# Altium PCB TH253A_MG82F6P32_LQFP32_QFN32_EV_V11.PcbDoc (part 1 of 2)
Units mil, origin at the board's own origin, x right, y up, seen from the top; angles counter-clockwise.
Board outline 3818.9 x 2637.8 mil, 2 copper layers (Top Layer, Bottom Layer); 102 components, 120 nets, 494 pads, 219 vias.
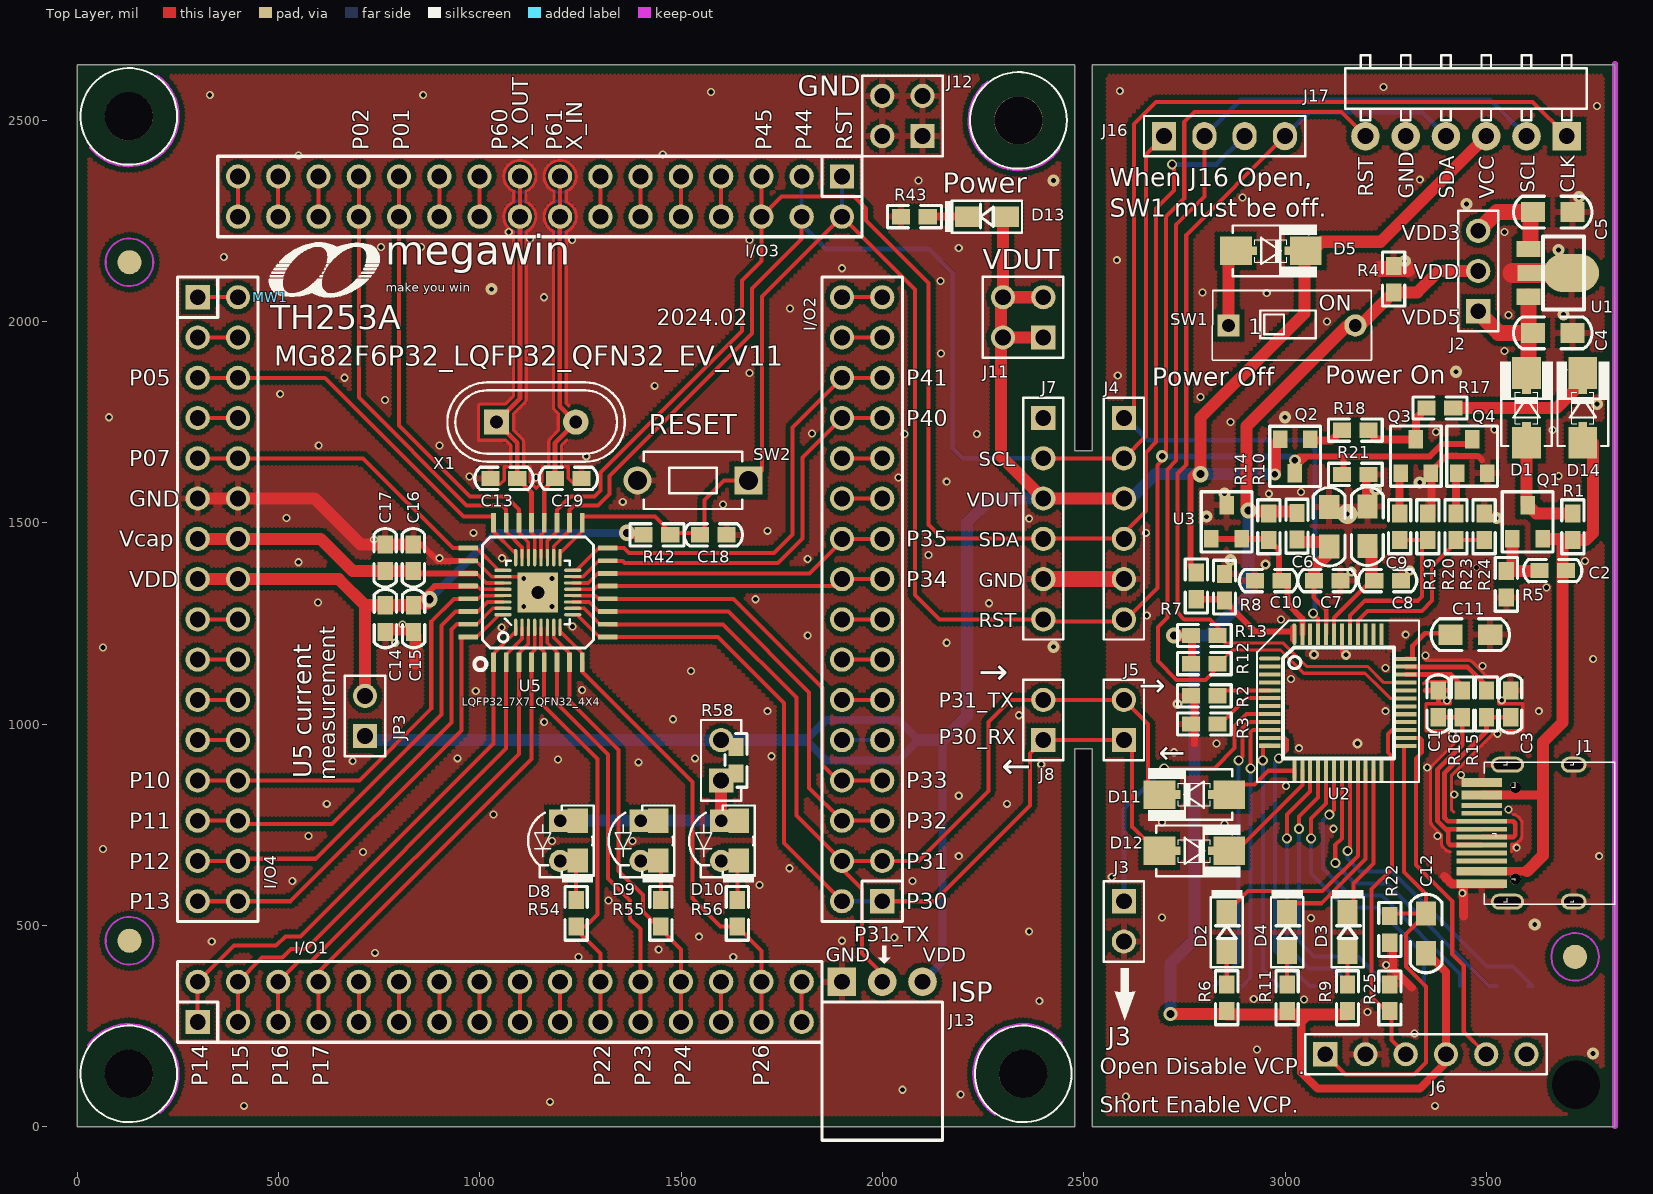
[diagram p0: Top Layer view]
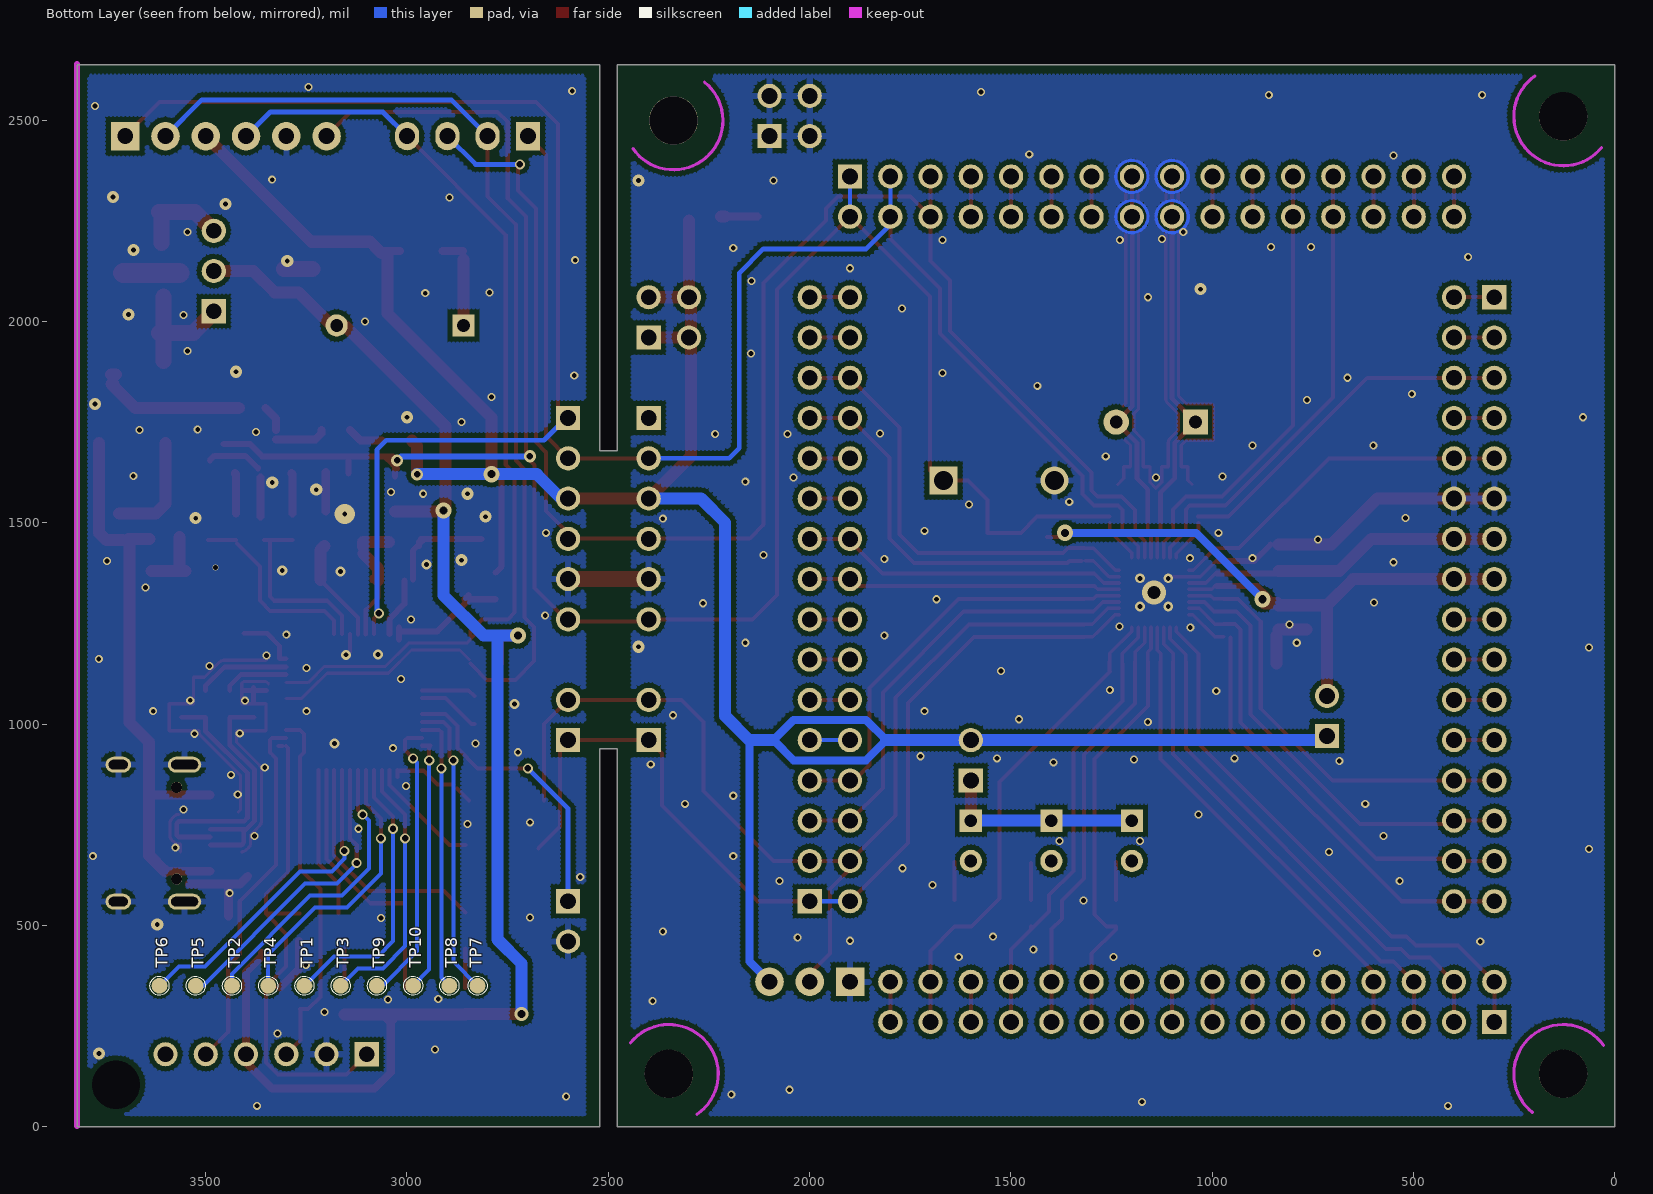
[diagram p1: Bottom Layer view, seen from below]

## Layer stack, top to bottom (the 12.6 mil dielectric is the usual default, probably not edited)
Top Layer: signal copper 1.4
Dielectric: dielectric 12.6, FR-4, Dk 4.8
Bottom Layer: signal copper 1.4

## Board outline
0,0 0,2637.8 2477.8,2637.8 2477.8,1678.74 2521.1,1678.74 2521.1,2637.8 3818.9,2637.8 3818.9,0 2521.1,0 2521.1,938.74 2477.8,938.74 2477.8,0

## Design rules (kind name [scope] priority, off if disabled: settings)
Clearance 12 [All] p1 off: gap=12
Clearance 7 [All] p2 off: gap=7
Clearance 6 [All] p3: gap=6
HoleSize 500-HoleSize [All] p1: absolutevalues=TRUE maxlimit=1500 minlimit=1 maxpercent=80.000 minpercent=20.000
PolygonConnect VIA [ISVIA] p1: connectstyle=Direct reliefconductorwidth=10 reliefentries=4 polygonreliefangle="90 Angle"
PolygonConnect "15 PolygonConnect" [All] p2: connectstyle=Relief reliefconductorwidth=15 reliefentries=4 polygonreliefangle="90 Angle"
RoomDefinition 1_MLink_V13 [InComponentClass('1_MLink_V13')] p1: confinementstyle=ConfineIn formatcopy=TRUE lockcomponents=FALSE outline -60,-105 3910,-105 3910,2750 -60,2750
RoomDefinition 2_TH253A_MG82F6P32_LQFP32_EV_V11 [InComponentClass('2_TH253A_MG82F6P32_LQFP32_EV_V11')] p2: confinementstyle=ConfineIn formatcopy=TRUE lockcomponents=FALSE outline -110,-40 3960,-40 3960,2710 -110,2710
RoutingVias [All] p1: holewidth=16 width=28 viastyle="Through Hole" minholewidth=16 minwidth=25 maxholewidth=28 maxwidth=50
ShortCircuit [All] p1 off: allowed=FALSE
SilkscreenOverComponentPads [All] p1: minsilkscreentomaskgap=10
SolderMaskExpansion [All] p1: expansion=4
UnRoutedNet [All] p1 off:
Width [All] p1: maxlimit=100 minlimit=6 preferedwidth=10
24 further rules are at their usual default settings.

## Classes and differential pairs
component class 2_TH253A_MG82F6P32_LQFP32_EV_V11: C13 C14 C15 C16 C17 C18 C19 D8 D9 D10 D13 I/O1 I/O2 I/O3 I/O4 J7 J8 J11 J12 J13 JP3 JP4 R42 R43 R54 R55 R56 R58 SW2 U5 X1
component class 1_MLink_V13: C1 C2 C3 C4 C5 C6 C7 C8 C9 C10 C11 C12 D1 D2 D3 D4 D5 D11 D12 D14 J1 J2 J3 J4 J5 J6 J16 J17 MW1 Q1 Q2 Q3 Q4 R1 R2 R3 R4 R5 R6 R7 R8 R9 R10 R11 R12 R13 R14 R15 R16 R17 R18 R19 R20 R21 R22 R23 R24 R25 SW1 TP1 TP2 TP3 TP4 TP5 TP6 TP7 TP8 TP9 TP10 U1 U2 U3

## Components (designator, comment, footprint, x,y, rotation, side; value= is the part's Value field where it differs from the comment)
C1 "15pF" 0603C#1 3380,1050 r270 top
C2 "0.1uF" 0603C#1 3664.41,1381.26 r0 top
C3 "15pF" 0603C#1 3560,1050 r270 top
C4 "4.7uF" 0805C 3664.41,1971.26 r0 top
C5 "4.7uF" 0805C 3664.41,2271.26 r0 top
C6 "4.7uF" 0805C 3109.41,1490 r90 top
C7 "0.1uF" 0603C#1 3104.45,1356.26 r0 top
C8 "0.1uF" 0603C#1 3254.45,1356.26 r0 top
C9 "4.7uF" 0805C 3204.41,1491.26 r90 top
C10 "0.1uF" 0603C#1 2958.5,1356.26 r0 top
C11 "4.7uF" 0805C 3460,1221.9 r0 top
C12 "4.7uF" 0805C 3350,480 r90 top
C13 "NC" 0603C#1 1060,1610 r0 top (schematic designator C18)
C14 "10uF" 0603C#2 765.55,1262 r270 top
C15 "0.1uF" 0603C#2 835.55,1262 r270 top
C16 "0.1uF" 0603C#2 835,1413 r90 top
C17 "4.7uF" 0603C#2 765,1413 r90 top
C18 "4.7uF" 0603C#2 1580,1470 r0 top (schematic designator C13)
C19 "NC" 0603C#1 1220,1610 r180 top
D1 "1N5817" DIODE_SMA_SOD323 3599.41,1785 r90 top
D2 "Yellow" 0805D 2855,483.26 r90 top
D3 "Green" 0805D 3155,483.26 r90 top
D4 "Red" 0805D 3005,483.26 r90 top
D5 "1N5817" DIODE_SMA_SOD323 2964.41,2175 r0 top
D8 "Red" LED38+0805 1199.45,710 r270 top
D9 "Yellow" LED38+0805 1399.45,710 r270 top
D10 "Green" LED38+0805 1599.45,710 r270 top
D11 "1N5817" DIODE_SMA_SOD323 2774.45,825 r180 top
D12 "1N5817" DIODE_SMA_SOD323 2774.45,685 r0 top
D13 "Yellow" 0805D 2259.45,2260 r180 top
D14 "1N5817" DIODE_SMA_SOD323 3739.41,1785 r90 top
I/O1 "CON16X2" PS16X2P254 299.45,260 r0 top locked
I/O2 "CON16X2" PS16X2P254 1999.45,560 r90 top locked
I/O3 "CON16X2" PS16X2P254 1899.45,2360 r180 top locked
I/O4 "CON16X2" PS16X2P254 299.45,2060 r270 top locked
J1 "CJ-USB3-C16P" USB_CF_16_SMD 3523.69,729.12 r90 top
J2 "2&3 (0 ohm)" PS3P254 3479.45,2025 r90 top
J3 "VCP Option" PS2P254 2599.45,560 r270 top locked
J4 "OnBoard ICP/SWD Connector" PS6P254 2599.45,1760 r270 top locked
J5 "NC" PS2P254 2599.45,960 r90 top locked
J6 "CON6" PS6P254 3099.45,180 r0 top
J7 "CON6" PS6P254 2399.45,1760 r270 top locked
J8 "NC" PS2P254 2399.45,960 r90 top
J11 "VDUT" PS2X2P254 2399.45,1960 r90 top
J12 "GND" PS2X2P254 2099.45,2460 r90 top
J13 "3P2.54_F_90" PS3P254f_90 1899.45,360 r0 top
J16 "When J16 Open, SW1 must be off." PS4P254 2699.45,2460 r0 top locked
J17 "Off Board ICP/SWD Connector" PS6P254_90 3699.45,2460 r180 top locked
JP3 "JUMPER_2" ps2p254 715,970 r90 top
MW1 "MW-A4" MEGAWIN_3.4 479.45,2060 r0 top
Q1 "IRLML6402" SOT23 3601.95,1501.97 r0 top
Q2 "2N3906" SOT23 3024.91,1665 r180 top
Q3 "3904" SOT23_132 3324.45,1665 r0 top
Q4 "3904" SOT23_132 3464.45,1665 r0 top
R1 "NC" 0603R 3714.45,1490 r270 top
R2 "0" 0603R 2799.45,1070 r0 top
R3 "NC" 0603R 2799.45,1000 r0 top
R4 "3.3K" 0603R 3269.45,2105 r270 top
R5 "1M" 0603R 3549.45,1347 r270 top
R6 "1K" 0603R 2855,320.26 r270 top
R7 "30K" 0603R 2779.45,1343 r90 top
R8 "10K" 0603R 2849.45,1340 r270 top
R9 "1K" 0603R 3155,320.26 r270 top
R10 "10" 0603R 3029.41,1491.26 r90 top
R11 "1K" 0603R 3005,320.26 r270 top
R12 "1.5K" 0603R 2799.45,1150 r180 top
R13 "1.5K" 0603R 2799.45,1220 r180 top
R14 "1K" 0603R 2959.41,1490 r270 top
R15 "30" 0603R 3500,1050 r90 top
R16 "30" 0603R 3440,1050 r90 top
R17 "4.7K" 0603R 3384.41,1785 r0 top
R18 "1K" 0603R 3174.45,1730 r0 top
R19 "4.7K" 0603R 3284.45,1490 r270 top
R20 "10K" 0603R 3354.45,1490 r270 top
R21 "1M" 0603R 3174.45,1620 r180 top
R22 "47K" 0603R 3260,490 r270 top
R23 "4.7K" 0603R 3424.45,1490 r270 top
R24 "10K" 0603R 3494.45,1490 r270 top
R25 "47K" 0603R 3260,320 r270 top
R42 "47K" 0603R 1440,1470 r180 top (schematic designator R27)
R43 "1K" 0603R 2079.45,2260 r180 top
R54 "470" 0603R 1239.45,530 r270 top
R55 "470" 0603R 1449.45,530 r270 top
R56 "470" 0603R 1639.45,530 r270 top
R58 "0" PS2p254+0603 1599.45,860 r90 top
SW1 "SW KEY-SPST" DIP2_SW 2859.49,1990 r0 top
SW2 "SW TACT-SPST" SW_T_2P 1529.45,1605 r180 top
TP1 "T POINT A" PIN1_1H0 3254.45,350 r90 bottom
TP2 "T POINT A" PIN1_1H0 3434.45,350 r90 bottom
TP3 "T POINT A" PIN1_1H0 3164.45,350 r180 bottom
TP4 "T POINT A" PIN1_1H0 3344.45,350 r180 bottom
TP5 "T POINT A" PIN1_1H0 3524.45,350 r180 bottom
TP6 "T POINT A" PIN1_1H0 3614.45,350 r180 bottom
TP7 "T POINT A" PIN1_1H0 2824.45,350 r180 bottom
TP8 "T POINT A" PIN1_1H0 2894.45,350 r180 bottom
TP9 "T POINT A" PIN1_1H0 3074.45,350 r180 bottom
TP10 "T POINT A" PIN1_1H0 2984.45,350 r90 bottom
U1 "AIC1734-33(SOT-89)" SOT89 3604.41,2120.31 r270 top
U2 "MG84FG516_LQFP48" LQFP48_7X7_050 3130.92,1054.39 r270 top
U3 "TL431A" SOT23 2854.41,1501.97 r0 top
U5 "MG82F6P32_LQFP32(7x7p0.8)+QFN32(4X4P0.4)" QFP32_7X7_QFN32_4X4 1144.25,1326.77 r90 top locked
X1 "NC" X49U 1140,1750 r0 top locked

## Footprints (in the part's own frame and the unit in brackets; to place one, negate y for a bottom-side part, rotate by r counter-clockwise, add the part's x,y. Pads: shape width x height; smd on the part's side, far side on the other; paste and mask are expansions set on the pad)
0603C#1 [mil]
  rect 45x38 smd: 1(33,0) 2(-33,0)
  silkscreen extent -72,-28 72,28
0603C#2 [mil]
  rect 45x38 smd: 1(-33,0) 2(33,0)
  silkscreen extent -72,-28 72,28
0603R [mil]
  rect 45x38 smd: 1(33,0) 2(-33,0)
  silkscreen extent -67,-28 67,28
0805C [mil]
  rect 60x50 smd: 1(-49.21,0) 2(49.21,0)
  silkscreen extent -97,-39 97,39
0805D [mil]
  rect 60x50 smd: 1(-49.21,0) 2(49.21,0)
  silkscreen extent -87,-40 104,40
DIODE_SMA_SOD323 [mm]
  rect 2x1.8 smd: 1(-2.2,0) 2(2.2,0)
  rect 0.95x0.54 smd: 1(-1.35,0) 2(1.35,0)
  silkscreen extent -2.4,-1.68 2.92,1.68
DIP2_SW [mm]
  rect 1.4x1.4 hole 0.8: 1(0,0)
  round 1.4 hole 0.8: 2(8,0)
  silkscreen extent -1.02,-2.2 9.02,2.2
LED38+0805 [mm]
  rect 1.4x1.4 hole 0.8: 1(-1.27,0)
  rect 1.524x1.27 smd: 1(-1.267,1.11) 2(1.233,1.11)
  round 1.4 hole 0.8: 2(1.27,0)
  silkscreen extent -2.23,-2.02 2.64,2.13
LQFP48_7X7_050 [mm]
  oval 0.254x1.35 smd: 1(-2.75,-4.292)
  rect 0.254x1.35 smd: 2(-2.25,-4.292) 3(-1.75,-4.292) 4(-1.25,-4.292) 5(-0.75,-4.292) 6(-0.25,-4.292) 7(0.25,-4.292) 8(0.75,-4.292) 9(1.25,-4.292) 10(1.75,-4.292) 11(2.25,-4.292) 12(2.75,-4.292) 25(2.763,4.292) 26(2.263,4.292) 27(1.763,4.292) 28(1.263,4.292) 29(0.763,4.292) 30(0.263,4.292) 31(-0.237,4.292) 32(-0.737,4.292) 33(-1.237,4.292) 34(-1.737,4.292) 35(-2.237,4.292) 36(-2.737,4.292)
  rect 1.35x0.254 smd: 13(4.286,-2.744) 14(4.286,-2.244) 15(4.286,-1.744) 16(4.286,-1.244) 17(4.286,-0.744) 18(4.286,-0.244) 19(4.286,0.256) 20(4.286,0.756) 21(4.286,1.256) 22(4.286,1.756) 23(4.286,2.256) 24(4.286,2.756) 37(-4.286,2.756) 38(-4.286,2.256) 39(-4.286,1.756) 40(-4.286,1.256) 41(-4.286,0.756) 42(-4.286,0.256) 43(-4.286,-0.244) 44(-4.286,-0.744) 45(-4.286,-1.244) 46(-4.286,-1.744) 47(-4.286,-2.244)
  oval 1.35x0.254 smd: 48(-4.286,-2.744)
  silkscreen extent -5.15,-5.09 5.05,5.11
MEGAWIN_3.4 [mil]
  silkscreen extent -2,0 272,135
PIN1_1H0 [mm]
  round 1 smd: 1(0,0)
  silkscreen extent -0.6,-0.6 0.6,0.6
PS2P254 [mil]
  rect 60x60 hole 39.37: 1(0,0)
  round 60 hole 39.37: 2(100,0)
  silkscreen extent -50,-50 150,50
ps2p254 [mil]
  rect 60x60 hole 39.37: 1(0,0)
  round 60 hole 39.37: 2(100,0)
  silkscreen extent -50,-50 150,50
PS2p254+0603 [mil]
  rect 60x60 hole 39.37: 1(0,0)
  rect 45x38 smd: 1(17,-36.85) 2(83,-36.85)
  round 60 hole 39.37: 2(100,0)
  silkscreen extent -50,-64 150,50
PS2X2P254 [mil]
  rect 60x60 hole 39.37: 1(0,0)
  round 60 hole 39.37: 2(0,100) 3(100,0) 4(100,100)
  silkscreen extent -50,-50 150,150
PS3P254 [mil]
  rect 60x60 hole 39.37: 1(0,0)
  round 60 hole 39.37: 2(100,0) 3(200,0)
  silkscreen extent -50,-50 250,50
PS3P254f_90 [mm]
  rect 1.8x1.8 hole 1: 1(0,0)
  round 1.8 hole 1: 2(2.54,0) 3(5.08,0)
  silkscreen extent -1.27,-10 6.35,-1.27
PS4P254 [mil]
  rect 60x70 hole 39.37: 1(0,0)
  oval 60x70 hole 39.37: 2(100,0) 3(200,0) 4(300,0)
  silkscreen extent -50,-50 350,50
PS6P254 [mil]
  rect 60x60 hole 39.37: 1(0,0)
  round 60 hole 39.37: 2(100,0) 3(200,0) 4(300,0) 5(400,0) 6(500,0)
  silkscreen extent -50,-50 550,50
PS6P254_90 [mm]
  rect 1.8x1.8 hole 1: 1(0,0)
  round 1.8 hole 1: 2(2.54,0) 3(5.08,0) 4(7.62,0) 5(10.16,0) 6(12.7,0)
  silkscreen extent -1.27,-5.11 13.97,-1
PS16X2P254 [mil]
  rect 60x60 hole 39.37: 1(0,0)
  round 60 hole 39.37: 2(0,100) 3(100,0) 4(100,100) 5(200,0) 6(200,100) 7(300,0) 8(300,100) 9(400,0) 10(400,100) 11(500,0) 12(500,100) 13(600,0) 14(600,100) 15(700,0) 16(700,100) 17(800,0) 18(800,100) 19(900,0) 20(900,100) 21(1000,0) 22(1000,100) 23(1100,0) 24(1100,100) 25(1200,0) 26(1200,100) 27(1300,0) 28(1300,100) 29(1400,0) 30(1400,100) 31(1500,0) 32(1500,100)
  silkscreen extent -50,-50 1550,150
QFP32_7X7_QFN32_4X4 [mm]
  rect 1.219x0.305 smd: 1(-4.4,2.8) 2(-4.4,2) 3(-4.4,1.2) 4(-4.4,0.4) 5(-4.4,-0.4) 6(-4.4,-1.2) 7(-4.4,-2) 8(-4.4,-2.8) 17(4.4,-2.8) 18(4.4,-2) 19(4.4,-1.2) 20(4.4,-0.4) 21(4.4,0.4) 22(4.4,1.2) 23(4.4,2) 24(4.4,2.8)
  oval 1.1x0.2 smd: 1(-2.2,1.4) 2(-2.2,1) 3(-2.2,0.6) 4(-2.2,0.2) 5(-2.2,-0.2) 6(-2.2,-0.6) 7(-2.2,-1) 8(-2.2,-1.4) 17(2.2,-1.4) 18(2.2,-1) 19(2.2,-0.6) 20(2.2,-0.2) 21(2.2,0.2) 22(2.2,0.6) 23(2.2,1) 24(2.2,1.4)
  rect 0.305x1.219 smd: 9(-2.8,-4.4) 10(-2,-4.4) 11(-1.2,-4.4) 12(-0.4,-4.4) 13(0.4,-4.4) 14(1.2,-4.4) 15(2,-4.4) 16(2.8,-4.4) 25(2.8,4.4) 26(2,4.4) 27(1.2,4.4) 28(0.4,4.4) 29(-0.4,4.4) 30(-1.2,4.4) 31(-2,4.4) 32(-2.8,4.4)
  oval 0.2x1.1 smd: 9(-1.4,-2.2) 10(-1,-2.2) 11(-0.6,-2.2) 12(-0.2,-2.2) 13(0.2,-2.2) 14(0.6,-2.2) 15(1,-2.2) 16(1.4,-2.2) 25(1.4,2.2) 26(1,2.2) 27(0.6,2.2) 28(0.2,2.2) 29(-0.2,2.2) 30(-0.6,2.2) 31(-1,2.2) 32(-1.4,2.2)
  rect 2.54x2.54 smd: G(0,0)
  Top Layer lines w0.229: -2.8,4.4 -2.8,3.841 -1.4,2.441 -1.4,2.2 ; -0.4,4.4 -0.4,3.758 -0.2,3.558 -0.2,2.2 ; 1.2,4.4 1.2,3.848 0.6,3.248 0.6,2.2 ; 2.8,4.4 2.8,3.867 1.4,2.467 1.4,2.2 ; 0.406,4.394 0.406,3.835 0.4,3.829 0.2,3.629 0.2,2.2 ; -2,4.349 -2,3.841 -1,2.841 -1,2.2 ; -1.2,4.349 -1.2,3.777 -0.6,3.177 -0.6,2.2 ; 2,4.349 2,3.911 1,2.911 1,1.073 ; -4.4,2.8 -3.867,2.8 -3.431,2.364 -2.467,1.4 -2.2,1.4 ; 4.4,2.8 3.841,2.8 2.441,1.4 2.2,1.4 ; -4.349,2 -3.911,2 -2.911,1 -2.2,1 ; 4.349,2 3.841,2 2.841,1 2.2,1 ; -4.4,1.2 -3.848,1.2 -3.248,0.6 -2.2,0.6 ; 4.349,1.2 3.777,1.2 3.177,0.6 2.2,0.6 ; -4.394,0.406 -3.835,0.406 -3.629,0.2 -2.2,0.2 ; 4.4,0.4 3.758,0.4 3.558,0.2 2.2,0.2 ; -2.2,-0.2 -3.558,-0.2 -3.758,-0.4 -4.4,-0.4 ; 2.2,-0.2 3.629,-0.2 3.829,-0.4 3.835,-0.406 4.394,-0.406 ; -2.2,-0.6 -3.177,-0.6 -3.777,-1.2 -4.349,-1.2 ; 2.2,-0.6 3.248,-0.6 3.848,-1.2 4.4,-1.2 ; -2.2,-1 -2.841,-1 -3.841,-2 -4.349,-2 ; 2.2,-1 2.911,-1 3.911,-2 4.349,-2 ; -2.2,-1.4 -2.441,-1.4 -3.841,-2.8 -4.4,-2.8 ; 2.2,-1.4 2.467,-1.4 3.867,-2.8 4.4,-2.8 ; -1.4,-2.2 -1.4,-2.467 -2.4,-3.467 -2.8,-3.867 -2.8,-4.4 ; -1,-2.2 -1,-2.911 -1.6,-3.512 -2,-3.911 -2,-4.349 ; -0.6,-2.2 -0.6,-2.448 -0.6,-3.248 -1.2,-3.848 -1.2,-4.4 ; -0.2,-2.2 -0.2,-3.629 -0.406,-3.835 -0.406,-4.394 ; 0.2,-2.2 0.2,-3.558 0.4,-3.758 0.4,-4.4 ; 0.6,-2.2 0.6,-3.177 1.2,-3.777 1.2,-4.349 ; 1,-2.2 1,-2.841 2,-3.841 2,-4.349 ; 1.4,-2.2 1.4,-2.441 2.8,-3.841 2.8,-4.4
  silkscreen extent -4.9,-3.5 3.5,4.01
SOT23 [mil]
  rect 36x43.31 smd: 1(-37.5,-41.97) 2(37.5,-41.97)
  rect 36x46.06 smd: 3(0.5,41.97)
  silkscreen extent -63,-74 63,75
SOT23_132 [mil]
  rect 36x43.31 smd: 1(-37.5,-41.97) 3(37.5,-41.97)
  rect 36x46.06 smd: 2(0.5,41.97)
  silkscreen extent -63,-74 63,75
SOT89 [mm]
  rect 1.016x1.5 smd: 1(-1.5,0) 3(1.5,0)
  oval 2.4x3.5 smd: 2(0,2.7)
  rect 1.016x2.6 smd: 2(0,0.6)
  silkscreen extent -2.3,0.9 2.3,3.5
SW_T_2P [mil]
  rect 70x70 hole 47.24: 1(-137.79,0)
  round 70 hole 47.24: 2(137.8,0)
  silkscreen extent -122,-71 122,71
USB_CF_16_SMD [mm]
  rect 0.55x3.2 smd: A1(-3.2,0.9) A4(-2.4,0.9)
  rect 0.3x3.2 smd: A5(-1.25,0.9) A6(-0.25,0.9) A7(0.25,0.9) B6(0.75,0.9) B7(-0.75,0.9) B8(-1.75,0.9)
  rect 0.3x2.54 smd: A8(1.25,0.9) B5(1.75,0.9)
  rect 0.55x2.54 smd: A9(2.4,0.9) A12(3.2,0.9)
  oval 1x2.1 hole 0.6 slot 1.7 at 90 deg: M1(-4.32,-0.718) M2(4.32,-0.718)
  oval 1x1.6 hole 0.6 slot 1.2 at 90 deg: M3(4.32,-4.898) M4(-4.32,-4.898)
  round 0.7 hole 0.7 unplated: M5(-2.89,-1.218) M6(2.89,-1.218)
  silkscreen extent -4.48,-7.5 4.55,0.74
X49U [mm]
  rect 1.6x1.6 hole 0.8: 1(-2.5,0)
  round 1.6 hole 0.8: 2(2.5,0)
  silkscreen extent -5.6,-2.5 5.6,2.5

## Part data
C1 C3 C7 C12: library part "CAP NP_Dup1"
C2 C8 C10: library part "CAP NP"
C4 C5: library part "C NP"
C6 C9 C11: library part CAP
C13 C14 C15 C16 C17 C18 C19: library part CAP, "Capacitor"
D1 D5 D11 D12 D14: library part "DIODE SCHOTTKY"
D2 D3 D4: library part Led0_0
D8 D9 D10 D13: library part LED
J1: "TPYE-C-9"
J2 J13: library part CON3
J3 J5 J8: library part CON2
J4 J17: library part CON6
J7: library part CON6_Dup1
J11 J12: library part CON2X2
J16: library part CON4
JP3: "Jumper"
MW1: library part MW_A4_2
Q1: library part "MOSFET P GSD"
Q2: library part 2N3906_0
Q3 Q4: library part "NPN BCE"
R1 R2 R3 R4: library part R_Dup4
R5 R6 R7 R8 R9 R11 R12 R13 R17 R18 R19 R22 R23 R25: library part R_Dup2
R10 R14 R15 R16: library part R_Dup5
R20 R21 R24: library part R_Dup1
R42: library part RES1
R43 R54 R55 R56 R58: library part R_Dup3
U1: library part AIC1722-33
U3: library part TL431/CYL
U5: library part MG82F6P32_LQFP32
X1: library part CRYSTAL

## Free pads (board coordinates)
  round 120 hole 120 unplated: 0(128.35,131.26) 0(128.35,2509.06) 0(2337.8,2499.06) 0(2349.45,131.26)
  round 60 smd mask+39.37: 0(130,461.9) 0(130,2146.9) 0(3720,421.9)
  round 100 hole 120 unplated: 0(3722.2,104.65)

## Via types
v1: diameter 20, hole 12, Top Layer to Bottom Layer, tented both sides, 164 vias
v2: diameter 30, hole 12, Top Layer to Bottom Layer, tented both sides, 19 vias
v3: diameter 25, hole 16, Top Layer to Bottom Layer, tented both sides, 13 vias
v4: diameter 25, hole 12, Top Layer to Bottom Layer, tented both sides, 7 vias
v5: diameter 40, hole 20, Top Layer to Bottom Layer, tented both sides, 5 vias
v6: diameter 24, hole 12, Top Layer to Bottom Layer, tented both sides, 4 vias
v7: diameter 30, hole 16, Top Layer to Bottom Layer, tented both sides, 3 vias
v8: diameter 50, hole 12, Top Layer to Bottom Layer, tented both sides, 1 vias
v9: diameter 35, hole 20, Top Layer to Bottom Layer, tented both sides, 1 vias
v10: diameter 15, hole 12, Top Layer to Bottom Layer, tented both sides, 1 vias
v11: diameter 60, hole 32, Top Layer to Bottom Layer, tented both sides, 1 vias

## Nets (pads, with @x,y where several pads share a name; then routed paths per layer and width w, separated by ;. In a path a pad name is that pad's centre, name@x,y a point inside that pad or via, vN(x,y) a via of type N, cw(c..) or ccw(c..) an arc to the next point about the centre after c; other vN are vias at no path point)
2.495V: C10.1 R14.1 U2.47 U3.1 U3.2 | length 416.4
  Top Layer w15: U3.1@2814.41,1460 U3.1@2816.91,1460 U3.2@2891.91,1460 2959.41,1460 R14.1@2964.41,1460 ; R14.1@2960,1456 R14.1@2970,1446 ; R14.1@2970,1442 R14.1@2970,1446 ; R14.1@2970,1452 R14.1@2970,1446 ; C10.1@2985,1359 2985,1431 R14.1@2970,1446 ; C10.1@3006,1357 3006,1356.26 3006,1298.45 3042.59,1261.86 U2.47@3042.59,1223.13
516P24: TP7.1 U2.9 | length 742.8
  Top Layer w10: v3(2884.45,910) 2894.45,920 2894.45,990 2909.63,1005.18 U2.9@2961.93,1005.18
  Bottom Layer w10: TP7.1@2824.45,350 2884.45,410 v3(2884.45,910)
516P25: TP8.1 U2.10 | length 688
  Top Layer w10: v3(2914.45,890) 2914.45,980 2919.94,985.49 U2.10@2961.93,985.49
  Bottom Layer w10: TP8.1@2894.45,350 2914.45,370 v3(2914.45,890)
516P26: TP9.1 U2.11 | length 717
  Top Layer w10: U2.11@2961.93,965.81 2998.64,965.81 3004.45,960 3004.45,935 v3(2984.45,915)
  Bottom Layer w10: v3(2984.45,915) 2974.45,905 2974.45,435.95 3060.4,350 TP9.1@3074.45,350
516P27: TP10.1 U2.12 | length 634.3
  Top Layer w10: v3(2944.45,910) 2944.45,943.23 2941.56,946.12 U2.12@2961.93,946.12
  Bottom Layer w10: v3(2944.45,910) 2944.45,390 TP10.1@2984.45,350
516P32: TP3.1 U2.15 | length 662
  Top Layer w10: v3@3004.45,715 v3(3004.45,716.26) 3004.45,775 3062.27,832.82 U2.15@3062.27,885.65
  Bottom Layer w10: v3@3004.45,715 3004.45,448.38 3059.83,393 3121.45,393 TP3.1@3164.45,350
516P33: TP1.1 U2.16 | length 710.4
  Top Layer w10: v3(3034.45,740) 3034.45,770 3081.96,817.51 U2.16@3081.96,885.65
  Bottom Layer w10: v3(3034.45,740) 3034.45,460.8 3072.25,423 3181.45,423 TP1.1@3254.45,350
516P34: TP4.1 U2.17 | length 713.1
  Top Layer w10: v3@3064.45,715 v3(3064.45,716.26) 3064.45,765 3101.64,802.19 U2.17@3101.64,885.65
  Bottom Layer w10: v3@3064.45,715 3064.45,628.7 3149.15,544 3227.72,544 3344.45,427.27 TP4.1@3344.45,350
516P35: TP2.1 U2.18 | length 733.6
  Top Layer w10: v3@3109.72,775.28 3121.33,786.88 U2.18@3121.33,885.65
  Bottom Layer w10: v3@3109.72,775.28 3094.45,760 3094.45,641.12 3161.57,574 3240.15,574 3434.45,379.7 TP2.1@3434.45,350
  other v3: 3110,775
516P36: TP5.1 U2.19 | length 774.1
  Top Layer w10: v3@3124.45,655 3124.45,699.45 3141.01,716.01 U2.19@3141.01,885.65
  Bottom Layer w10: v3@3124.45,655 3124.45,653.55 3174,604 3252.57,604 3506.57,350 TP5.1@3524.45,350 TP5.1@3515,350
  other v3: 3125,655
516P37: TP6.1 U2.20 | length 822.9
  Top Layer w10: v3@3154.45,685 v3(3155,685) 3160.7,690.7 U2.20@3160.7,885.65
  Bottom Layer w10: v3@3154.45,685 3154.45,665.98 3186.43,634 3265,634 3501,398 3566.45,398 TP6.1@3614.45,350 TP6.1@3605,350
CHIP_VDD: C14.1 C15.1 I/O4.15 I/O4.16 JP3.2 R42.1 U5.28 | length 1590.4
  Top Layer w10: v5@1370,1465 1407,1465 R42.1@1410.51,1465
  Top Layer w12: v5@865,1302.41 v5@875,1302.41
  Top Layer w15: C15.1@845,1300 865,1320 887.52,1342.52 U5.28@971.02,1342.52 U5.28@988.5,1342.52
  Top Layer w30: I/O4.15@299.45,1360 I/O4.16@399.45,1360 650,1360 715,1295 ; JP3.2@715,1070 715,1295 ; C15.1@835.55,1295 C14.1@765.55,1295 715,1295 ; C15.1@838.53,1300 845,1300 v5@870,1300
  Bottom Layer w20: v5(875,1310) 1040,1475 v5(1365.93,1475)
D+: C3.1 J1.A6 J1.B6 R15.2 | length 648.6
  Top Layer w12: J1.A6@3488.25,719.27 3566.78,719.27 3571.5,724 3571.5,753 3565.86,758.64 J1.B6@3488.25,758.64 3404.36,758.64 3396,767 3396,878.54 3500,982.54 R15.2@3500,1017 C3.1@3560,1017
D-: C1.1 J1.A7 J1.B7 R16.2 | length 590.1
  Top Layer w12: C1.1@3380,1017 R16.2@3440,1017 3440,948 3378,886 3378,759.54 3404.16,733.39 ; 3400,738.96 3410.4,738.96 ; 3405,734.23 3405,705.23 3410.64,699.59 J1.B7@3488.25,699.59 ; 3405.35,733.9 3410.4,738.96 ; J1.A7@3488.25,738.96 3410.4,738.96
DET_VDUT: R7.2 R8.1 U2.48 | length 318.6
  Top Layer w15: R7.2@2779.45,1310 2849.45,1310 R8.1@2857.01,1310 ; R8.1@2847.01,1320 R8.1@2854.73,1312.28 ; R8.1@2847.21,1307.24 2848.45,1306 2924.45,1230 3015.39,1230 ; U2.48@3019.45,1210 3019.45,1223.13 U2.48@3019.45,1240
DUT_CLK: J4.1 J17.1 U2.45 | length 2846.4
  Top Layer w10: J4.1@2599.45,1760 2624.45,1785 2624.45,2490 2679.45,2545 3614.45,2545 J17.1@3699.45,2460 ; v3(3069.33,1275) 3081.96,1262.37 U2.45@3081.96,1223.13
  Bottom Layer w12: J4.1@2599.45,1760 2604.45,1760 2659.45,1705 3050.67,1705 3074.41,1681.26 3074.41,1280.08 v3(3069.33,1275)
DUT_RST: C18.1 I/O3.1 I/O3.2 J4.6 J7.6 J17.6 Q2.3 Q4.2 R21.1 R42.2 SW2.1 U5.17 | length 5628.7
  Top Layer w10: U5.17@1255,1515 1435,1515 1475,1475 1547,1475 1557.93,1475 1557.93,1557 1605.93,1605 SW2.1@1667.24,1605 ; SW2.1@1667.24,1630 1700.93,1630 1700.93,2061.48 I/O3.2@1899.45,2260 2080.45,2079 2080.45,1320.9 2141.35,1260 J7.6@2399.45,1260 ; J7.6@2399.45,1255 J4.6@2599.45,1255 ; J4.6@2602.45,1257 2683.2,1337.75 2683.2,1642.75 2699.95,1659.5 2704.45,1664 2704.45,1665 2704.45,2260 2749.45,2305 2749.45,2495 2774.45,2520 3139.45,2520 J17.6@3199.45,2460
  Top Layer w15: Q2.3@3024.41,1635 Q2.3@3029.41,1640 ; v7(3024.41,1655) 3034.41,1665 3054.41,1665 ; Q2.3@3029.41,1615 3029.41,1623.03 Q2.3@3029.41,1640 ; v7@3029.41,1658 3029.41,1655 Q2.3@3029.41,1640 ; R21.1@3144.41,1622 3144.41,1665 ; Q4.2@3455.03,1695 3389.41,1695 3359.41,1665 3144.41,1665 ; Q2.3@3029.41,1640 3034.41,1645 3054.41,1665 ; 3054.41,1665 3144.41,1665
  Bottom Layer w10: I/O3.2@1899.45,2260 I/O3.1@1899.45,2360
  Bottom Layer w15: v7(2694.45,1665) 3014.41,1665 v7(3024.41,1655)
FAIL: D4.2 U2.22 | length 461.4
  Top Layer w10: D4.2@3005,555 3090.28,555 3200.07,664.78 U2.22@3200.07,885.65
GND_POWER: C1.2 C3.2 C4.2 C5.2 C6.2 C7.1 C8.1 C9.2 C10.2 C11.2 C13.2 C14.2 C15.2 C16.2 C17.2 C18.2 C19.2 I/O4.11 I/O4.12 J1.A1 J1.A12 J1.M1 J1.M2 J1.M3 J1.M4 J3.2 J4.5 J6.2 J7.5 J12.1 J12.2 J12.3 J12.4 J13.1 J17.5 Q3.3 Q4.3 R2.2 R3.2 R4.2 R5.1 R8.2 R20.2 R21.2 R22.1 R24.2 R25.2 R43.1 SW2.2 U1.2 U2.42 U3.3 U5.26 U5.G | length 8534.7
  Top Layer w8: 1045,1795 1063.95,1795 1083.45,1814.5 1083.45,2223.34 cw(c1099.45,2260) 1084.45,2297.08 1084.45,2322.92 cw(c1099.45,2360) 1139.45,2360 cw(c1099.45,2360) 1114.45,2322.92 1114.45,2297.08 cw(c1099.45,2260) 1115.45,2223.34 1115.45,1807.87 cw(c1099.45,1807.87) 1110.76,1796.56 1084.6,1770.4 1084.6,1729.6 1104.3,1709.9 cw(c1093,1698.58) 1109,1698.58 1109,1639 1125.5,1639 1125.5,1600.13 1139.82,1585.81 ; 1050,1595 1060.5,1605.5 1060.5,1639 1077,1639 1077,1691.95 1063.95,1705 996.58,1705 996.58,1790 1001.58,1795 1060,1795 ; 1140,1585.63 1154.5,1600.13 1154.5,1639 1171,1639 1171,1698.58 ; 1216.05,1705 1203,1691.95 1203,1639 1219.5,1639 1219.5,1610.5 C19.2@1235,1595 ; 1221.05,1790 1214.74,1796.31 1214.74,2223.04 ccw(c1199.45,2260) 1214.45,2297.08 1214.45,2322.92 ccw(c1199.45,2360) 1239.45,2360 ccw(c1199.45,2360) 1184.45,2322.92 1184.45,2297.08 ccw(c1199.45,2260) 1182.74,2223.66 1182.74,1783.06 1195,1770.8 1195,1729.2 1175.69,1709.89 ; 3343.48,1099.79 3349.48,1105.79 3405.17,1105.79 3410,1100.96 3410,1050.5 3350,1050.5 3350,983.5 3410,983.5 3423,983.5 3423,955.04 3365.98,898.02 ccw(c3378.02,885.98) 3361.02,885.98 3361,759.54 ; v1@3344,1164 3349.53,1158.47 3453.53,1158.47 ; 3398.62,687.57 ccw(c3410.64,699.59) 3410.64,682.59 cw(c3410.64,699.59) 3398.6,687.59 3393,693.19 ; 3419,781.64 3413,787.64 3413,871.5 3432.93,891.43 3512,970.5 ; 3465.55,1153.49 ccw(c3453.53,1141.47) 3453.53,1158.47 ; 3517,983.5 3530,983.5 3590,983.5 3590,1050.5 3530,1050.5 3530,1116.5 3502.54,1116.5 3465.57,1153.47 ccw(c3453.53,1141.47) 3453.53,1158.47 ; 3562.24,682.68 3562.24,702.27 3566.78,702.27 ; 3583.52,711.98 ccw(c3571.5,724) 3588.5,724 ; 3583.52,765.02 cw(c3571.5,753) 3588.5,753 ; 1171,1698.58 cw(c1187,1698.58) 1175.69,1709.89 ; 1171,1698.58 cw(c1187,1698.58) 1175.7,1709.9 ; 3361,759.54 ccw(c3378,759.54) 3366,747.5 ; 3361,759.54 ccw(c3378,759.54) 3365.98,747.52 ; 3366,747.5 3378,735.5 3388,725.5 3388,705.23 ; 3388,705.23 ccw(c3405,705.23) 3392.98,693.21 ; 3388,705.23 ccw(c3405,705.23) 3393,693.19 ; 3512,970.5 ccw(c3500,982.54) 3517,982.54 cw(c3500,982.54) 3512.02,970.52 ; 3566.78,702.27 ccw(c3566.78,719.27) 3578.8,707.25 ; 3566.78,702.27 ccw(c3566.78,719.27) 3578.82,707.27 ; 3577.88,770.66 ccw(c3565.86,758.64) 3565.86,775.64 cw(c3565.86,758.64) 3577.9,770.64 ; 3577.9,770.64 3583.51,765.04 cw(c3571.5,753) 3588.5,753 ; 3578.82,707.27 3583.51,711.96 ccw(c3571.5,724) 3588.5,724 ; 3588.5,724 3588.5,753
  Top Layer w10: 3141.01,1179.01 U2.42@3141.01,1223.13
  Top Layer w12: 3348,1083 3408,1083 ; 3381,1054 C1.2@3381,1091
  Top Layer w15: 855,1446 895.49,1405.51 924.49,1405.51 U5.26@971.02,1405.51 U5.26@985.27,1405.51 ; Q3.3@3369.7,1635.29 3400.65,1666.24 3478.11,1666.24 3489.35,1655
  Top Layer w20: 2775.45,951.9 R2.2@2775.45,1067.53 ; C9.2@3201.45,1528 R21.2@3201.45,1625.53 ; R22.1@3268,461 3268,391.89 3314.49,345.4 ; R20.2@3363.45,1515 Q3.3@3363.45,1612.53
  Top Layer w22: 3395,621.9 3413.79,603.12 J1.A1@3488.25,603.12 J1.A1@3540,603.12 ; 3442.88,522.79 J1.A1@3442.88,597.25
  Top Layer w30: I/O4.11@302,1560 I/O4.12@399.45,1560 590,1560 704,1446 C17.2@765,1446 C16.2@835,1446 ; C14.2@765.55,1235 C15.2@835.55,1235 ; 840,1150.05 C15.2@840,1220.05
  Top Layer w40: J7.5@2399.45,1360 J4.5@2599.45,1360 ; 3234.35,2130 3305.45,2130
  Top Layer w50: 3564.41,2120.31 U1.2@3628.03,2120.31 U1.2@3704.41,2120.31
  Bottom Layer w8: 1139.45,2260 ccw(c1099.45,2260) 1139.45,2260 ; 1139.45,2360 ccw(c1099.45,2360) 1139.45,2360 ; 1239.45,2260 ccw(c1199.45,2260) 1239.45,2260 ; 1239.45,2360 ccw(c1199.45,2360) 1239.45,2360
  other v1: 414.45,51.9 3372,51.9 1174.45,61.9 2604.35,75 2194.35,80 2049.45,91.9 2930,191.9 3321,231.9 3204.35,285 2389.45,311.9 3047,316 2922,317 3251,401.9 1245,421.9 1629.45,421.9 739.45,431.9 1444.35,440 334.35,460 1899.45,461.9 2029.45,470 1544.45,471.9 2364.35,485 3064.35,518 2694.35,520 1320,561.9 3440,580 1694.35,600 534.35,610 2074.35,610 2569.45,620 1769.45,641.9 2189.45,671.9 3780,671.9 710,681.9 64.35,690 3575,693 1179.45,710 1379.45,710 575,721.9 3378,722 3120,740 2849.45,751.9 2694.35,756 1034.35,775 3555,788 620,801.9 2309.45,801.9 2189.45,821.9 3420,825 3002.45,846 3437,874 3353,891.9 2394.35,900 1394.35,905 684.35,908 1194.45,911.9 944.35,915 1534.35,915 1724.35,920 2724.35,930 3034.35,940 2829.41,951.9 3527,976 3415,977 1160,1005 1480,1011.9 2339.45,1021.9 1714.45,1031.9 3249.45,1031.9 3630,1031.9 3402,1058 3538,1059 990,1081.9 1254.35,1085 3014.45,1111.9 1524.45,1131.9 3249,1139 3490,1144 3765,1161.9 3349,1170 64.35,1190 790,1201.9 2159.45,1201.9 1814.35,1220 3299.45,1221.9 1054.35,1240 1230,1241.9 807.99,1247 2989.45,1260 2656.41,1269.26 2264.35,1300 598,1301.9 1684.35,1310 3649,1339 550,1401.9 3744.35,1405 1814.35,1410 900,1411.9 1055,1411.9 2114.35,1420 737.44,1458 984.35,1475 2654.35,1475 1714.35,1480 2364.35,1510 520,1511.9 1604.35,1545 1355,1551.9 2959.41,1571.9 3039.41,1576.26 2159.45,1601.9 1140,1611.9 2039.45,1611.9 974.35,1615 3679.41,1616.26 1264.35,1665 600,1691.9 900,1691.9 2054.35,1720 2234.35,1720 1825,1721.9 3374.35,1725 3664.35,1730 3519.41,1731.9 2864.35,1750 79.45,1761.9 764.35,1805 2789.45,1811.9 504.35,1820 1434.35,1840 664.35,1860 2584.35,1866 1670,1871.9 2145,1920 3544.41,1926.26 3104.35,2000 3554.35,2016.26 1770,2031.9 1159.45,2060 2954.35,2070 2794.45,2071.9 2144.35,2100 1899.45,2131.9 2582,2151.9 364.35,2160 2189.45,2181.9 754.35,2185 854.35,2185 1229.45,2201.9 1669.45,2201.9 1124.35,2205 1071.92,2221.9 3544.41,2221.9 2894.35,2308 2089.45,2350 3334.45,2351.9 549.45,2411.9 1454.35,2415 3774.35,2535 329.45,2561.9 859.45,2561.9 1574.35,2570 2589.41,2571.9 3244.41,2581.9
  other v2: 3764.45,181.9 3620,501.9 2424.45,1191.9 2864.41,1406.93 3524.41,1511.26 2804.35,1515 2849.45,1571.9 3225,1582 3334.35,1600 2999.41,1761.9 3774.35,1795 3424.41,1875 3691.45,2016.9 1029.45,2080 3297.01,2150 3679,2177 3450,2291.9 3730,2309 2424.35,2350
  other v4: 3180,952 2732.52,1050 3151.45,1172 3071.45,1173 3165,1379 3309.41,1381.26 2951,1396
  other v6: 1109.25,1291.77 1179.25,1291.77 1109.25,1361.77 1179.25,1361.77
  other v8: 3154.41,1521.26
  other v10: 3475,1389
  other v11: 1144.25,1326.77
